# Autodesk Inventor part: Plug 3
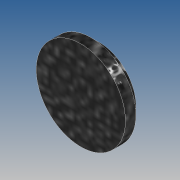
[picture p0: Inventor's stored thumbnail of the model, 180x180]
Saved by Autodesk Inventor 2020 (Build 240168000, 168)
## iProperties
Created: 2019-10
Part Number: Plug 3
Material: Generic
Document SubType Name: Modeling
Designer: yello
Density: 1 g/cm^3
Appearance: Default
Author: yello
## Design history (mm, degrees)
sketch "Sketch1"
  geometry: C1 r 4.25 at (0, 0); 1 further point
  constraints: 1 centre point, 1 coincident
  dimensions: "d0" = 8.5 diameter of C1
extrude "Extrusion1" new body sketch "Sketch1" distance "d1" = 1; taper "d2" = 0 deg
sketch "Sketch2"
  geometry: C1 r 3.5 at (0, 0); 1 further point
  constraints: 1 centre point, 1 coincident
  dimensions: "d3" = 7 diameter of C1
extrude "Extrusion2" join sketch "Sketch2" distance "d4" = 0.75; taper "d5" = 0 deg
body "Solid1"
